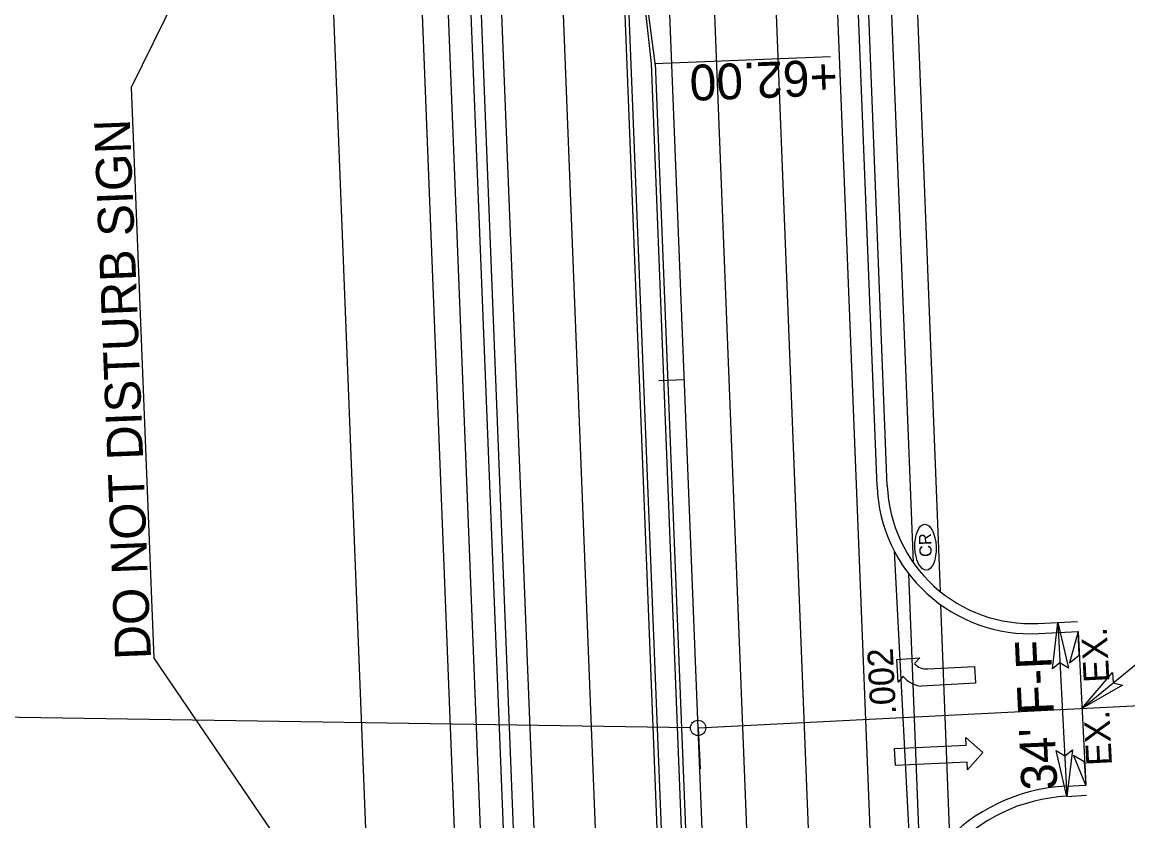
# Model space of a CAD drawing. Extents: x 1627861 to 1629601, y 761281 to 766239.
# Drawn here: x 1628338.3 to 1628554.1, y 762489 to 762644.9 of the extents above; entities that cross this region are included whole.
import ezdxf

# ---------------------------------------------------------------- set-up
doc = ezdxf.new("R2010")
doc.units = 0
for name, color, linetype in [('Default', 7, 'Continuous'), ('Exist Property Tie Line Text', 7, 'Continuous'), ('Exist Right of Way Line Leader', 7, 'Continuous'), ('Exist Right of Way Monument Leader', 7, 'Continuous'), ('Exist Right of Way Monument Text', 7, 'Continuous'), ('Exist Utilities Gas Meter CELL', 7, 'Continuous'), ('Exist Utilities Gas Meter Cogo Elevation', 7, 'Continuous'), ('Exist Utilities Gas Meter Cogo Number', 7, 'Continuous'), ('Exist Utilities Gas UG Line', 7, 'Continuous'), ('Exist Utilities Other Unknown UG SUE Text', 7, 'Continuous'), ('Exist Utilities Power UG Cable SUE LOS B Cogo Point CELL', 7, 'Continuous'), ('Exist Utilities Telephone UG Cable SUE LOS B Cogo Comment', 7, 'Continuous'), ('Exist Utilities Water Fire Hydrant Cogo Elevation', 7, 'Continuous'), ('Exist Utilities Water Fire Hydrant Cogo Number', 7, 'Continuous'), ('Exist Utilities Water Meter Cogo Elevation', 7, 'Continuous'), ('Exist Utilities Water UG Line SUE LOS B Cogo Number', 7, 'Continuous'), ('Exist Utilities Water Valve CELL', 7, 'Continuous'), ('Scratch_Level_0', 7, 'Continuous'), ('Typical Terminator CELL', 7, 'Continuous')]:
    doc.layers.add(name, color=color, linetype=linetype)

msp = doc.modelspace()

# ---------------------------------------------------------------- linework, layer by layer
at = {"layer": 'Default'}
msp.add_line((1628490.95, 762493.09), (1628490.95, 762493.09), dxfattribs=at)
at = {"layer": 'Exist Property Tie Line Text'}
msp.add_line((1628467.57, 762575.08), (1628462.58, 762574.88), dxfattribs=at)
at = {"layer": 'Exist Right of Way Line Leader'}
msp.add_line((1628468.75, 762507.18), (1628307.04, 762509.67), dxfattribs=at)
msp.add_circle((1628470.25, 762507.16), 1.5, dxfattribs=at)
at = {"layer": 'Exist Right of Way Monument Leader'}
for p, q in [((1628509.01, 762520.52), (1628513.5, 762520.81)), ((1628509.29, 762516.12), (1628509.01, 762520.52)), ((1628513.5, 762520.81), (1628512.51, 762519.7)), ((1628515.06, 762518.69), (1628524.2, 762519.17)), ((1628524.2, 762519.17), (1628524.38, 762515.88)), ((1628510.29, 762517.23), (1628509.29, 762516.12)), ((1628524.38, 762515.88), (1628513.84, 762515.32)), ((1628522.59, 762503.79), (1628522.52, 762505.29)), ((1628522.52, 762505.29), (1628525.81, 762502.34)), ((1628508.6, 762503.14), (1628522.59, 762503.79)), ((1628508.76, 762499.84), (1628508.6, 762503.14)), ((1628525.81, 762502.34), (1628522.81, 762499)), ((1628522.74, 762500.5), (1628508.76, 762499.84)), ((1628522.81, 762499), (1628522.74, 762500.5))]:
    msp.add_line(p, q, dxfattribs=at)
for centre, radius, start, end in [((1628514.88, 762521.94), 3.28, 223.403, 273.0612), ((1628514.36, 762520.53), 5.25, 219.0734, 264.3851)]:
    msp.add_arc(centre, radius, start, end, dxfattribs=at)
at = {"layer": 'Exist Right of Way Monument Text'}
for p, q in [((1628505.17, 762554.34), (1628492.5, 762875.6)), ((1628447.23, 762158.21), (1628426.86, 762674.72)), ((1628536.67, 762525.56), (1628544.39, 762525.96)), ((1628542.1, 762495.8), (1628545.92, 762496))]:
    msp.add_line(p, q, dxfattribs=at)
for centre, radius, start, end in [((1628535.15, 762555.53), 30, 182.2582, 272.9208), ((1628543.88, 762460.85), 35, 92.9208, 182.2582)]:
    msp.add_arc(centre, radius, start, end, dxfattribs=at)
at = {"layer": 'Exist Utilities Gas Meter CELL'}
for p, q in [((1628486.22, 762102.11), (1628373.12, 764970.45)), ((1628470.25, 762507.16), (1628638.33, 762515.73)), ((1628470.25, 762507.16), (1628638.33, 762515.73))]:
    msp.add_line(p, q, dxfattribs=at)
at = {"layer": 'Exist Utilities Gas Meter Cogo Elevation'}
for p, q in [((1628507.17, 762554.42), (1628494.5, 762875.66)), ((1628445.23, 762158.13), (1628424.87, 762674.64)), ((1628536.57, 762527.56), (1628544.29, 762527.96)), ((1628542.2, 762493.8), (1628546.02, 762494))]:
    msp.add_line(p, q, dxfattribs=at)
for centre, radius, start, end in [((1628535.15, 762555.53), 28, 182.2582, 272.9208), ((1628543.88, 762460.85), 33, 92.9208, 182.2582)]:
    msp.add_arc(centre, radius, start, end, dxfattribs=at)
at = {"layer": 'Exist Utilities Gas Meter Cogo Number'}
for points in [[(1628539.38, 762518.69), (1628540.47, 762527.76), (1628542.53, 762518.8), (1628540.87, 762519.87)], [(1628553.1, 762515.48), (1628545.15, 762510.98), (1628551.15, 762517.95), (1628551.27, 762515.98)], [(1628543.29, 762502.87), (1628542.2, 762493.8), (1628540.14, 762502.76), (1628541.8, 762501.69)]]:
    msp.add_lwpolyline(points, close=True, dxfattribs=at)
at = {"layer": 'Exist Utilities Gas UG Line'}
for p, q in [((1628504.58, 762163.21), (1628465.73, 763148.45)), ((1628516.57, 762163.69), (1628477.72, 763148.92)), ((1628451.12, 762161.11), (1628412.27, 763146.34)), ((1628463.11, 762161.58), (1628424.26, 763146.81)), ((1628480.18, 762477.5), (1628471.51, 762697.33)), ((1628462.69, 762476.81), (1628454.26, 762690.64)), ((1628461.88, 762636.9), (1628457.95, 762666.77)), ((1628461.88, 762636.9), (1628468.19, 762477.02))]:
    msp.add_line(p, q, dxfattribs=at)
at = {"layer": 'Exist Utilities Other Unknown UG SUE Text'}
for p, q in [((1628455.01, 762690.67), (1628463.44, 762476.84)), ((1628461.13, 762636.87), (1628457.95, 762666.77)), ((1628467.44, 762476.99), (1628461.13, 762636.87))]:
    msp.add_line(p, q, dxfattribs=at)
at = {"layer": 'Exist Utilities Telephone UG Cable SUE LOS B Cogo Comment'}
for p, q in [((1628513.66, 762478.51), (1628511.35, 762537.26)), ((1628519.38, 762485.84), (1628517.59, 762531.2))]:
    msp.add_line(p, q, dxfattribs=at)
at = {"layer": 'Exist Utilities Water Fire Hydrant Cogo Elevation'}
msp.add_ellipse((1628514.63, 762542.42), major_axis=(-0.18, 4.48), ratio=0.462467, dxfattribs=at)
at = {"layer": 'Exist Utilities Water Fire Hydrant Cogo Number'}
msp.add_line((1628420.61, 762102.01), (1628396.89, 762704.96), dxfattribs=at)
at = {"layer": 'Exist Utilities Water Meter Cogo Elevation'}
msp.add_line((1628470.25, 762507.16), (1628470.66, 762499.17), dxfattribs=at)
at = {"layer": 'Exist Utilities Water UG Line SUE LOS B Cogo Number'}
for p, q in [((1628508.54, 762541.66), (1628511.94, 762475.15)), ((1628544.39, 762525.96), (1628545.92, 762496))]:
    msp.add_line(p, q, dxfattribs=at)
at = {"layer": 'Exist Utilities Water Valve CELL'}
for p, q in [((1628503.08, 762899.21), (1628517.49, 762533.79)), ((1628512.26, 762539.39), (1628498.34, 762892.48)), ((1628433.36, 762218.24), (1628415.37, 762674.25)), ((1628420.37, 762674.47), (1628438.36, 762218.21))]:
    msp.add_line(p, q, dxfattribs=at)
at = {"layer": 'Scratch_Level_0'}
for p, q in [((1628386.99, 762687.86), (1628359.62, 762632.19)), ((1628461.73, 762636.89), (1628496.11, 762638.25)), ((1628359.62, 762632.19), (1628364.02, 762520.77)), ((1628545.15, 762510.98), (1628618.1, 762570.65)), ((1628540.47, 762527.76), (1628542.2, 762493.8)), ((1628364.02, 762520.77), (1628404.83, 762460.84))]:
    msp.add_line(p, q, dxfattribs=at)
at = {"layer": 'Typical Terminator CELL'}
for points in [[(1628544.39, 762525.96), (1628542.7, 762519.86), (1628544.62, 762521.34)], [(1628545.92, 762496), (1628543.49, 762501.84), (1628545.59, 762500.61)]]:
    msp.add_lwpolyline(points, close=True, dxfattribs=at)

# ---------------------------------------------------------------- texts
at = {"layer": 'Exist Utilities Power UG Cable SUE LOS B Cogo Point CELL'}
for s, rotation, p in [('DO NOT DISTURB SIGN', 92.2582, (1628363.51, 762520.63)), ("34' F-F", 92.5655, (1628540.37, 762495.17))]:
    msp.add_text(s, height=7, rotation=rotation, dxfattribs=at).set_placement(p)
at = {"layer": 'Exist Utilities Water Fire Hydrant Cogo Elevation'}
msp.add_text('CR', height=2.4, rotation=92.2582, dxfattribs=at).set_placement((1628515.88, 762540.58))
at = {"layer": 'Exist Utilities Water UG Line SUE LOS B Cogo Number'}
for s, p in [('EX.', (1628550.52, 762516.13)), ('.002', (1628508.89, 762509.87)), ('EX.', (1628551.03, 762499.91))]:
    msp.add_text(s, height=5, rotation=92.9208, dxfattribs=at).set_placement(p)
at = {"layer": 'Scratch_Level_0'}
msp.add_text('+62.00', height=7, rotation=182.2582, dxfattribs=at).set_placement((1628497.33, 762637.7))

doc.saveas('drawing.dxf')
